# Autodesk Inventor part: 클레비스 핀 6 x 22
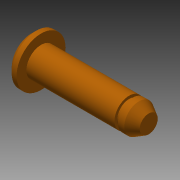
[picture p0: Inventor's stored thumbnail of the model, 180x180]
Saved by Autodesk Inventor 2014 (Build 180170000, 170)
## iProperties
IsCustomPart: 1
Created: 2017-08
Part Number: 클레비스 핀 6 x 22
Material: 강철
Description: 머리가 있는 클레비스 핀
Document SubType Name: Modeling
Standard: ISO 2341
Designer: mduedu
Standard Revision: Second edition 1986-11-01
Standards Organization: ISO
Language: ko-KR
Size Designation: B - 6 x 24
Categories: <MemberInstance><Categories><Category DisplayName="조임쇠" InternalName="e4da775c-781d-43d5-af7c-5136215cf5a6" Mnemonic="FSTN"><Category DisplayName="핀" InternalNa
Density: 7.85 g/cm^3
Appearance: Orange
Author: mduedu
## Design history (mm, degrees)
sketch "스케치1"
  geometry: L1 (-2, 0)-(-2, 5); L2 (-2, 5)-(0, 5); L3 (0, 5)-(0, 3); L4 (0, 3)-(22, 3); L5 (22, 3)-(22, 0); L6 (-2, 0)-(22, 0); L7 (-7, 0)-(28, 0) reference; L8 (0, -1.96)-(0, 6.16) reference; C1 r 0.8 at (18.8, 0)
  constraints: 12 end point, 3 parallel, 2 collinear, 2 perpendicular, 1 centre point, 1 point on line, 1 vertical
  dimensions: "d0" = 6 diameter of L4 L6 (= NND); "d1" = 10 diameter of L2 L6 (= KOD); "d2" = 2 distance of L1.end L2.end (= KOH); "d3" = 22 distance of L3.end L4.end (= NLG); "d5" = 3.2 distance from line of L5 C1.centre (= DIST); "d6" = 1.6 diameter of C1 (= BOR)
revolve "본체" stored, may be unused: angle "d4" = 90 deg
node "작업 평면4"
sketch "스케치2"
  geometry: C1 r 3 at (0, 0) reference; C2 r 2.425 at (0, 0); 1 further point
  constraints: 1 centre point, 1 coincident
  dimensions: "d33" = 4.85 diameter of C2
extrude "돌출2" cut sketch "스케치2" distance "d34" = 0.7; taper "d35" = 0 deg
workplane "Work Plane5"
body "Solid1"
chamfer "모따기1" distance "d9" = 1 (= PHH2); stored, may be unused: angle "d10" = 45 deg (= FAWI2), second distance "d16" = 1 (= PHH2)
chamfer "모따기2" distance "d11" = 2 (= PHH1); stored, may be unused: angle "d12" = 30 deg (= FAWI1), second distance "d17" = 2 (= PHH1)
workplane "Work Plane1"
other parameters: "PHH1" = 2 [user parameter; used in 2 equation terms], "PHH2" = 1 [user parameter; used in 2 equation terms], "KOD" = 10 [user parameter; used in 1 equation term], "KOH" = 2 [user parameter; used in 1 equation term], "NND" = 6 [user parameter; used in 1 equation term], "FAWI1" = 30 deg [user parameter; used in 1 equation term], "FAWI2" = 45 deg [user parameter; used in 1 equation term], "DIST" = 3.2 [user parameter; used in 1 equation term], "BOR" = 1.6 [user parameter; used in 1 equation term], "NLG" = 22 [user parameter; used in 1 equation term], "d13" = 0, "d14" = 0, "d30" = 0, "d32" = 18
